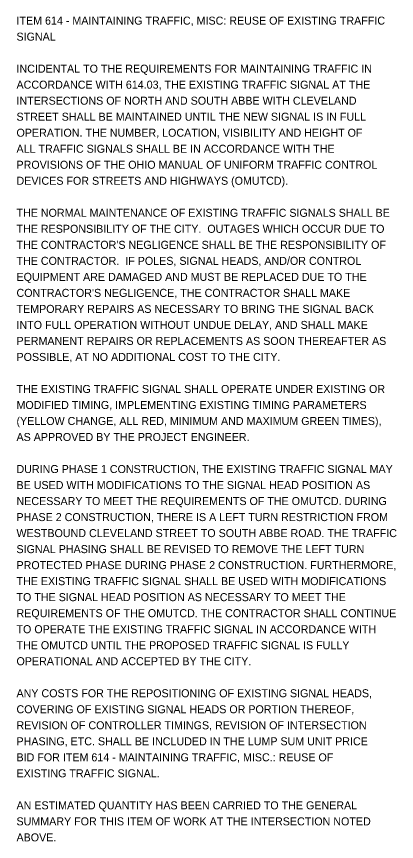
# Model space of a CAD drawing. Extents: x 0 to 71.8, y 0 to 22.
# Drawn here: x 35.89 to 42.54, y 1.12 to 15.54 of the extents above; entities that cross this region are included whole.
import ezdxf

# ---------------------------------------------------------------- set-up
doc = ezdxf.new("R2010")
doc.units = 0
doc.layers.add('SH_Text', color=7, linetype='Continuous')

msp = doc.modelspace()

# ---------------------------------------------------------------- texts
at = {"layer": 'SH_Text'}
for s, p in [('ITEM 614 - MAINTAINING TRAFFIC, MISC: REUSE OF EXISTING TRAFFIC ', (35.887, 15.4)), ('SIGNAL ', (35.887, 15.12)), ('INCIDENTAL TO THE REQUIREMENTS FOR MAINTAINING TRAFFIC IN ', (35.887, 14.56)), ('ACCORDANCE WITH 614.03, THE EXISTING TRAFFIC SIGNAL AT THE ', (35.887, 14.28)), ('INTERSECTIONS OF NORTH AND SOUTH ABBE WITH CLEVELAND ', (35.887, 14)), ('STREET SHALL BE MAINTAINED UNTIL THE NEW SIGNAL IS IN FULL ', (35.887, 13.72)), ('OPERATION. THE NUMBER, LOCATION, VISIBILITY AND HEIGHT OF ', (35.887, 13.44)), ('ALL TRAFFIC SIGNALS SHALL BE IN ACCORDANCE WITH THE ', (35.887, 13.16)), ('PROVISIONS OF THE OHIO MANUAL OF UNIFORM TRAFFIC CONTROL ', (35.887, 12.88)), ('DEVICES FOR STREETS AND HIGHWAYS (OMUTCD).', (35.887, 12.6)), ('THE NORMAL MAINTENANCE OF EXISTING TRAFFIC SIGNALS SHALL BE ', (35.887, 12.04)), ('THE RESPONSIBILITY OF THE CITY.  OUTAGES WHICH OCCUR DUE TO ', (35.887, 11.76)), ("THE CONTRACTOR'S NEGLIGENCE SHALL BE THE RESPONSIBILITY OF ", (35.887, 11.48)), ('THE CONTRACTOR.  IF POLES, SIGNAL HEADS, AND/OR CONTROL ', (35.887, 11.2)), ('EQUIPMENT ARE DAMAGED AND MUST BE REPLACED DUE TO THE ', (35.887, 10.92)), ("CONTRACTOR'S NEGLIGENCE, THE CONTRACTOR SHALL MAKE ", (35.887, 10.64)), ('TEMPORARY REPAIRS AS NECESSARY TO BRING THE SIGNAL BACK ', (35.887, 10.36)), ('INTO FULL OPERATION WITHOUT UNDUE DELAY, AND SHALL MAKE ', (35.887, 10.08)), ('PERMANENT REPAIRS OR REPLACEMENTS AS SOON THEREAFTER AS ', (35.887, 9.8)), ('POSSIBLE, AT NO ADDITIONAL COST TO THE CITY.', (35.887, 9.52)), ('THE EXISTING TRAFFIC SIGNAL SHALL OPERATE UNDER EXISTING OR ', (35.887, 8.96)), ('MODIFIED TIMING, IMPLEMENTING EXISTING TIMING PARAMETERS ', (35.887, 8.68)), ('(YELLOW CHANGE, ALL RED, MINIMUM AND MAXIMUM GREEN TIMES), ', (35.887, 8.4)), ('AS APPROVED BY THE PROJECT ENGINEER.  ', (35.887, 8.12)), ('DURING PHASE 1 CONSTRUCTION, THE EXISTING TRAFFIC SIGNAL MAY ', (35.887, 7.56)), ('BE USED WITH MODIFICATIONS TO THE SIGNAL HEAD POSITION AS ', (35.887, 7.28)), ('NECESSARY TO MEET THE REQUIREMENTS OF THE OMUTCD. DURING ', (35.887, 7)), ('PHASE 2 CONSTRUCTION, THERE IS A LEFT TURN RESTRICTION FROM ', (35.887, 6.72)), ('WESTBOUND CLEVELAND STREET TO SOUTH ABBE ROAD. THE TRAFFIC ', (35.887, 6.44)), ('SIGNAL PHASING SHALL BE REVISED TO REMOVE THE LEFT TURN ', (35.887, 6.16)), ('PROTECTED PHASE DURING PHASE 2 CONSTRUCTION. FURTHERMORE, ', (35.887, 5.88)), ('THE EXISTING TRAFFIC SIGNAL SHALL BE USED WITH MODIFICATIONS ', (35.887, 5.6)), ('TO THE SIGNAL HEAD POSITION AS NECESSARY TO MEET THE ', (35.887, 5.32)), ('REQUIREMENTS OF THE OMUTCD. THE CONTRACTOR SHALL CONTINUE ', (35.887, 5.04)), ('TO OPERATE THE EXISTING TRAFFIC SIGNAL IN ACCORDANCE WITH ', (35.887, 4.76)), ('THE OMUTCD UNTIL THE PROPOSED TRAFFIC SIGNAL IS FULLY ', (35.887, 4.48)), ('OPERATIONAL AND ACCEPTED BY THE CITY.', (35.887, 4.2)), ('ANY COSTS FOR THE REPOSITIONING OF EXISTING SIGNAL HEADS, ', (35.887, 3.64)), ('COVERING OF EXISTING SIGNAL HEADS OR PORTION THEREOF, ', (35.887, 3.36)), ('REVISION OF CONTROLLER TIMINGS, REVISION OF INTERSECTION ', (35.887, 3.08)), ('PHASING, ETC. SHALL BE INCLUDED IN THE LUMP SUM UNIT PRICE ', (35.887, 2.8)), ('BID FOR ITEM 614 - MAINTAINING TRAFFIC, MISC.: REUSE OF ', (35.887, 2.52)), ('EXISTING TRAFFIC SIGNAL. ', (35.887, 2.24)), ('AN ESTIMATED QUANTITY HAS BEEN CARRIED TO THE GENERAL ', (35.887, 1.68)), ('SUMMARY FOR THIS ITEM OF WORK AT THE INTERSECTION NOTED ', (35.887, 1.4)), ('ABOVE.  ', (35.887, 1.12))]:
    msp.add_text(s, height=0.14, dxfattribs=at).set_placement(p)

doc.saveas('drawing.dxf')
